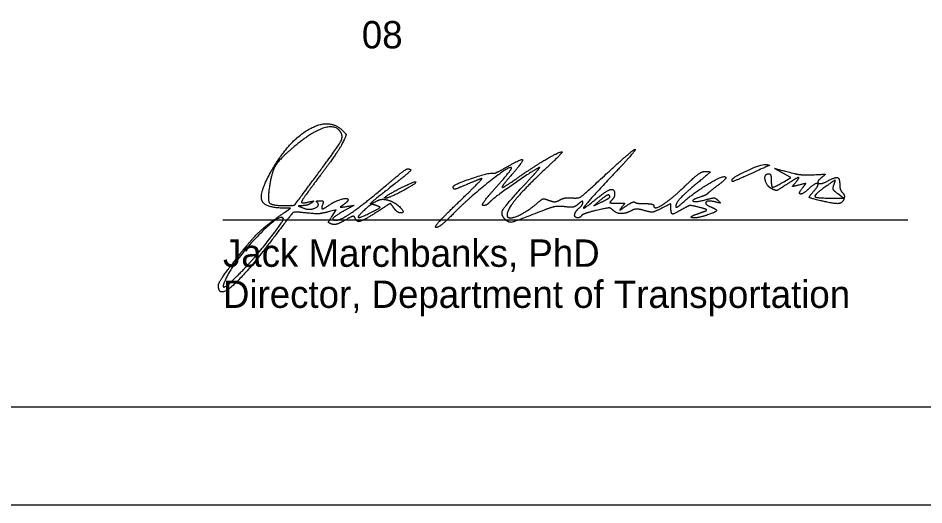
# Model space of a CAD drawing. Extents: x 39.5 to 73.5, y 15.6 to 37.6.
# Drawn here: x 65.326 to 69.955, y 15.601 to 18.089 of the extents above; entities that cross this region are included whole.
import ezdxf

# ---------------------------------------------------------------- set-up
doc = ezdxf.new("R2010")
doc.units = 0
for name, color, linetype in [('GM_X_City_Street', 7, 'Continuous'), ('GM_X_Hydro_Text', 7, 'Continuous'), ('GM_X_Interstate_Route', 7, 'Continuous'), ('GM_X_Major_River_Text', 7, 'Continuous')]:
    doc.layers.add(name, color=color, linetype=linetype)

msp = doc.modelspace()

# ---------------------------------------------------------------- linework, layer by layer
at = {"layer": 'GM_X_City_Street'}
msp.add_lwpolyline([(41.5012, 37.1011), (73.0012, 37.1011), (73.0012, 16.1011), (41.5012, 16.1011)], close=True, dxfattribs=at)
at = {"layer": 'GM_X_Hydro_Text'}
msp.add_lwpolyline([(39.5012, 15.6011), (73.5012, 15.6011), (73.5012, 37.6011), (39.5012, 37.6011)], close=True, dxfattribs=at)
at = {"layer": 'GM_X_Interstate_Route'}
for p, q in [((66.8356, 17.2629), (66.8356, 17.2629)), ((68.9749, 17.2621), (68.9749, 17.2621)), ((67.201, 17.1731), (67.201, 17.1731)), ((68.3499, 17.1751), (68.3499, 17.1751)), ((67.1562, 17.1314), (67.1562, 17.1314)), ((67.5728, 17.144), (67.5728, 17.144)), ((69.4274, 17.1558), (69.4274, 17.1558))]:
    msp.add_line(p, q, dxfattribs=at)
for points in [[(69.2387, 17.2525), (69.2751, 17.274), (69.2344, 17.297)], [(69.4874, 17.169), (69.5437, 17.1691), (69.515, 17.1912)], [(68.2982, 17.1554), (68.2687, 17.1298), (68.3093, 17.1495)], [(66.688, 17.096), (66.7187, 17.1172), (66.6808, 17.1179)], [(66.9309, 17.0761), (66.9521, 17.1085), (66.9104, 17.0984)]]:
    msp.add_lwpolyline(points, dxfattribs=at)
for points in [[(66.6243, 17.3137), (66.7106, 17.4641), (66.9187, 17.5801), (66.9844, 17.5144)], [(66.9754, 17.5052), (66.9494, 17.5473), (66.8234, 17.5061), (66.728, 17.4245)], [(66.8356, 17.2629), (66.957, 17.4264), (66.9894, 17.4826), (66.9754, 17.5052)], [(66.9844, 17.5144), (67.0031, 17.4957), (67.0032, 17.4906), (66.9849, 17.4522)], [(66.9849, 17.4522), (66.9739, 17.4292), (66.9222, 17.3536), (66.8699, 17.2843)], [(66.728, 17.4245), (66.6614, 17.3674), (66.6225, 17.3033), (66.6114, 17.2321)], [(67.8781, 17.2722), (67.9586, 17.3288), (68.0899, 17.406), (68.1056, 17.406)], [(68.1056, 17.406), (68.1105, 17.406), (68.0692, 17.3634), (68.0138, 17.3113)], [(68.3323, 17.2926), (68.4073, 17.3617), (68.4734, 17.4183), (68.4791, 17.4184)], [(68.4791, 17.4184), (68.4848, 17.4184), (68.4328, 17.3583), (68.3635, 17.2847)], [(67.8191, 17.3257), (67.8979, 17.3718), (67.9101, 17.3586), (67.8509, 17.2913)], [(66.6808, 17.1179), (66.5829, 17.1195), (66.5595, 17.2007), (66.6243, 17.3137)], [(67.2145, 17.2402), (67.2649, 17.2831), (67.3104, 17.3182), (67.3156, 17.3183)], [(67.3156, 17.3183), (67.3404, 17.3188), (67.3171, 17.2933), (67.2312, 17.226)], [(67.8472, 17.3254), (67.8376, 17.335), (67.6278, 17.1681), (67.5499, 17.0888)], [(67.9874, 17.325), (67.9384, 17.2972), (67.7501, 17.165), (67.7368, 17.149)], [(67.7535, 17.2964), (67.759, 17.2946), (67.7886, 17.3078), (67.8191, 17.3257)], [(67.7694, 17.225), (67.8157, 17.2768), (67.8507, 17.3219), (67.8472, 17.3254)], [(67.9223, 17.246), (67.9684, 17.2953), (67.9978, 17.3308), (67.9874, 17.325)], [(68.9749, 17.2621), (68.9749, 17.2745), (69.1278, 17.3448), (69.1467, 17.3411)], [(69.1467, 17.3411), (69.1674, 17.3371), (69.1681, 17.3375), (69.0465, 17.2828)], [(69.2344, 17.297), (69.1916, 17.3211), (69.1906, 17.3211), (69.2937, 17.2947)], [(66.8699, 17.2843), (66.8177, 17.2149), (66.7749, 17.1543), (66.7749, 17.1495)], [(67.5501, 17.2279), (67.5504, 17.2384), (67.7377, 17.3016), (67.7535, 17.2964)], [(67.5728, 17.144), (67.6438, 17.2125), (67.6991, 17.2685), (67.6957, 17.2685)], [(67.6957, 17.2685), (67.6923, 17.2685), (67.6633, 17.2573), (67.6312, 17.2435)], [(67.8509, 17.2913), (67.8229, 17.2595), (67.7999, 17.2298), (67.7999, 17.2253)], [(67.7999, 17.2253), (67.7999, 17.2209), (67.8351, 17.242), (67.8781, 17.2722)], [(68.0138, 17.3113), (67.9142, 17.2176), (67.8249, 17.1094), (67.8249, 17.0825)], [(68.1573, 17.1702), (68.1908, 17.1674), (68.2143, 17.1838), (68.3323, 17.2926)], [(68.3635, 17.2847), (68.2339, 17.1471), (68.2019, 17.0999), (68.284, 17.1676)], [(68.7218, 17.1451), (68.7754, 17.1939), (68.9224, 17.2839), (68.9393, 17.2783)], [(68.7406, 17.2363), (68.7858, 17.2801), (68.8229, 17.3058), (68.8406, 17.3054)], [(68.8406, 17.3054), (68.8649, 17.305), (68.8611, 17.2986), (68.8124, 17.2586)], [(68.9393, 17.2783), (68.9477, 17.2755), (68.9324, 17.2568), (68.9053, 17.2366)], [(69.0465, 17.2828), (68.9839, 17.2547), (68.9749, 17.2521), (68.9749, 17.2621)], [(69.176, 17.218), (69.1495, 17.2321), (69.1385, 17.2935), (69.1624, 17.2935)], [(69.1624, 17.2935), (69.1693, 17.2935), (69.1749, 17.2794), (69.1749, 17.2623)], [(69.2983, 17.2477), (69.3227, 17.2773), (69.307, 17.2735), (69.2507, 17.2363)], [(69.2937, 17.2947), (69.3143, 17.2894), (69.3593, 17.2867), (69.3937, 17.2886)], [(69.3937, 17.2886), (69.4486, 17.2917), (69.4534, 17.2901), (69.4336, 17.2753)], [(69.4336, 17.2753), (69.4047, 17.2538), (69.4277, 17.2374), (69.4614, 17.2554)], [(69.4614, 17.2554), (69.5016, 17.277), (69.5249, 17.2712), (69.5249, 17.2398)], [(66.6114, 17.2321), (66.6, 17.1587), (66.6214, 17.131), (66.6895, 17.131)], [(66.6895, 17.131), (66.7362, 17.131), (66.7407, 17.1351), (66.8356, 17.2629)], [(66.9531, 17.056), (66.9762, 17.056), (67.1022, 17.1448), (67.2145, 17.2402)], [(67.2312, 17.226), (67.138, 17.153), (67.1165, 17.1314), (67.1604, 17.1549)], [(67.201, 17.1731), (67.2214, 17.1909), (67.3534, 17.2567), (67.3586, 17.2516)], [(67.3586, 17.2516), (67.3647, 17.2454), (67.2221, 17.1685), (67.2045, 17.1685)], [(67.6312, 17.2435), (67.5686, 17.2167), (67.5498, 17.2131), (67.5501, 17.2279)], [(67.7035, 17.131), (67.6932, 17.131), (67.7221, 17.1723), (67.7694, 17.225)], [(67.8152, 17.0604), (67.79, 17.0856), (67.8189, 17.1357), (67.9223, 17.246)], [(68.5749, 17.1295), (68.5749, 17.1067), (68.6702, 17.1681), (68.7406, 17.2363)], [(68.8124, 17.2586), (68.7384, 17.1976), (68.6874, 17.1441), (68.6874, 17.1273)], [(68.9053, 17.2366), (68.8783, 17.2164), (68.8534, 17.1964), (68.8499, 17.1921)], [(69.1749, 17.2623), (69.1749, 17.2254), (69.1892, 17.2233), (69.2387, 17.2525)], [(69.2507, 17.2363), (69.2106, 17.2098), (69.1974, 17.2065), (69.176, 17.218)], [(69.3177, 17.236), (69.2847, 17.2277), (69.2828, 17.2288), (69.2983, 17.2477)], [(69.3378, 17.2252), (69.3524, 17.2428), (69.3502, 17.244), (69.3177, 17.236)], [(69.3665, 17.2165), (69.3346, 17.1865), (69.3116, 17.1936), (69.3378, 17.2252)], [(69.3917, 17.2038), (69.4222, 17.2375), (69.4005, 17.2484), (69.3665, 17.2165)], [(69.4952, 17.2367), (69.5051, 17.2625), (69.4969, 17.2594), (69.4343, 17.2138)], [(69.515, 17.1912), (69.4946, 17.2069), (69.4888, 17.2201), (69.4952, 17.2367)], [(69.5249, 17.2398), (69.5249, 17.2239), (69.5313, 17.2046), (69.5391, 17.1968)], [(67.2045, 17.1685), (67.1997, 17.1685), (67.1981, 17.1706), (67.201, 17.1731)], [(68.284, 17.1676), (68.3324, 17.2075), (68.3749, 17.2179), (68.3749, 17.1898)], [(68.3499, 17.1751), (68.3499, 17.1886), (68.3259, 17.1794), (68.2982, 17.1554)], [(68.3093, 17.1495), (68.3317, 17.1603), (68.3499, 17.1718), (68.3499, 17.1751)], [(68.3749, 17.1898), (68.3749, 17.1808), (68.3682, 17.1668), (68.3599, 17.1585)], [(68.8156, 17.1756), (68.766, 17.1601), (68.7855, 17.1465), (68.8374, 17.1603)], [(68.8499, 17.1921), (68.8465, 17.1879), (68.831, 17.1804), (68.8156, 17.1756)], [(69.4274, 17.1558), (69.3727, 17.1688), (69.367, 17.1765), (69.3917, 17.2038)], [(69.4343, 17.2138), (69.3916, 17.1827), (69.408, 17.1689), (69.4874, 17.169)], [(69.5391, 17.1968), (69.5469, 17.1891), (69.5499, 17.1739), (69.5457, 17.1631)], [(66.7812, 17.1304), (66.7588, 17.1295), (66.7592, 17.1282), (66.7854, 17.1177)], [(66.7749, 17.1495), (66.7749, 17.1447), (66.7904, 17.1444), (66.8093, 17.1488)], [(66.8249, 17.1441), (66.8146, 17.1371), (66.7949, 17.1309), (66.7812, 17.1304)], [(66.7854, 17.1177), (66.8152, 17.1058), (66.8715, 17.1303), (66.854, 17.1478)], [(66.8093, 17.1488), (66.8348, 17.1547), (66.8389, 17.1535), (66.8249, 17.1441)], [(66.854, 17.1478), (66.8495, 17.1523), (66.8558, 17.156), (66.8679, 17.156)], [(66.8679, 17.156), (66.8825, 17.156), (66.8876, 17.1496), (66.8829, 17.1373)], [(66.8829, 17.1373), (66.874, 17.114), (66.8868, 17.1133), (66.919, 17.1354)], [(66.919, 17.1354), (66.9479, 17.1552), (67.0124, 17.1727), (67.0124, 17.1607)], [(66.9908, 17.1367), (66.9719, 17.1229), (66.9739, 17.1216), (67.0064, 17.1265)], [(67.0124, 17.1607), (67.0124, 17.1562), (67.0027, 17.1454), (66.9908, 17.1367)], [(67.0064, 17.1265), (67.0432, 17.1321), (67.0431, 17.1318), (66.9976, 17.1067)], [(67.1562, 17.1314), (67.139, 17.1378), (67.1225, 17.1326), (67.1031, 17.1149)], [(67.1281, 17.0951), (67.1744, 17.1188), (67.178, 17.1234), (67.1562, 17.1314)], [(67.1604, 17.1549), (67.1731, 17.1617), (67.197, 17.1638), (67.2135, 17.1596)], [(67.2466, 17.1182), (67.2297, 17.1422), (67.2277, 17.1418), (67.1619, 17.0994)], [(67.2135, 17.1596), (67.2496, 17.1504), (67.308, 17.0935), (67.2813, 17.0935)], [(67.4624, 17.0192), (67.4521, 17.0194), (67.5018, 17.0756), (67.5728, 17.144)], [(67.7368, 17.149), (67.7286, 17.1391), (67.7136, 17.131), (67.7035, 17.131)], [(67.843, 17.0685), (67.8647, 17.0685), (67.946, 17.1137), (67.9824, 17.146)], [(67.9824, 17.146), (68.0027, 17.164), (68.0156, 17.1667), (68.0393, 17.1577)], [(68.1204, 17.125), (68.0911, 17.1288), (68.0513, 17.1223), (68.0148, 17.1079)], [(68.0393, 17.1577), (68.0595, 17.15), (68.0783, 17.1507), (68.0943, 17.1597)], [(68.0943, 17.1597), (68.1077, 17.1673), (68.1361, 17.172), (68.1573, 17.1702)], [(68.1899, 17.1395), (68.1742, 17.1253), (68.1529, 17.1209), (68.1204, 17.125)], [(68.2124, 17.147), (68.2124, 17.1541), (68.2023, 17.1507), (68.1899, 17.1395)], [(68.1937, 17.1185), (68.204, 17.1271), (68.2124, 17.1399), (68.2124, 17.147)], [(68.3599, 17.1585), (68.3483, 17.1468), (68.3542, 17.1435), (68.3865, 17.1435)], [(68.3865, 17.1435), (68.424, 17.1435), (68.4264, 17.1415), (68.4108, 17.1221)], [(68.4108, 17.1221), (68.3988, 17.1071), (68.4053, 17.1089), (68.4326, 17.128)], [(68.4326, 17.128), (68.454, 17.143), (68.4747, 17.1521), (68.4786, 17.1481)], [(68.4786, 17.1481), (68.4826, 17.1442), (68.5058, 17.141), (68.5304, 17.141)], [(68.5304, 17.141), (68.5549, 17.141), (68.5749, 17.1358), (68.5749, 17.1295)], [(68.6624, 17.1169), (68.6624, 17.1398), (68.6614, 17.1398), (68.6152, 17.117)], [(68.6874, 17.1273), (68.6874, 17.1199), (68.7029, 17.1279), (68.7218, 17.1451)], [(68.8076, 17.1219), (68.7687, 17.1318), (68.752, 17.1302), (68.7244, 17.1139)], [(68.8374, 17.1603), (68.8757, 17.1705), (68.891, 17.1699), (68.903, 17.1577)], [(68.8843, 17.1502), (68.8476, 17.1593), (68.8343, 17.1362), (68.8687, 17.123)], [(68.903, 17.1577), (68.9157, 17.1448), (68.9121, 17.1434), (68.8843, 17.1502)], [(69.5457, 17.1631), (69.5377, 17.142), (69.4965, 17.1395), (69.4274, 17.1558)], [(66.4371, 16.8538), (66.5147, 16.9542), (66.5948, 17.0315), (66.688, 17.096)], [(66.7692, 17.0961), (66.7358, 17.0994), (66.7241, 17.0889), (66.6474, 16.9873)], [(66.9104, 17.0984), (66.8701, 17.0886), (66.8477, 17.0883), (66.7692, 17.0961)], [(66.9976, 17.1067), (66.9466, 17.0785), (66.9268, 17.056), (66.9531, 17.056)], [(67.1619, 17.0994), (67.0931, 17.0551), (67.0556, 17.0453), (67.0475, 17.0697)], [(67.1031, 17.1149), (67.0588, 17.0744), (67.0701, 17.0655), (67.1281, 17.0951)], [(67.2813, 17.0935), (67.2717, 17.0935), (67.2561, 17.1046), (67.2466, 17.1182)], [(67.5499, 17.0888), (67.5121, 17.0503), (67.4728, 17.019), (67.4624, 17.0192)], [(68.0148, 17.1079), (67.8687, 17.0502), (67.8337, 17.0419), (67.8152, 17.0604)], [(67.8249, 17.0825), (67.8249, 17.0748), (67.8331, 17.0685), (67.843, 17.0685)], [(68.1867, 17.0685), (68.1683, 17.0685), (68.1729, 17.1013), (68.1937, 17.1185)], [(68.281, 17.106), (68.2427, 17.0968), (68.2084, 17.0846), (68.2049, 17.0789)], [(68.3653, 17.1081), (68.3542, 17.1192), (68.3342, 17.1187), (68.281, 17.106)], [(68.4617, 17.1056), (68.4309, 17.0891), (68.3831, 17.0904), (68.3653, 17.1081)], [(68.5261, 17.1057), (68.4993, 17.1134), (68.4762, 17.1133), (68.4617, 17.1056)], [(68.6152, 17.117), (68.5778, 17.0985), (68.5593, 17.0962), (68.5261, 17.1057)], [(68.7244, 17.1139), (68.6793, 17.0873), (68.6624, 17.0881), (68.6624, 17.1169)], [(68.8436, 17.081), (68.797, 17.0656), (68.7496, 17.0713), (68.7937, 17.087)], [(68.7937, 17.087), (68.8074, 17.0919), (68.8271, 17.099), (68.8374, 17.1027)], [(68.8374, 17.1027), (68.8488, 17.1069), (68.8371, 17.1144), (68.8076, 17.1219)], [(68.8687, 17.123), (68.8992, 17.1113), (68.8903, 17.0964), (68.8436, 17.081)], [(66.6809, 17.0667), (66.66, 17.0877), (66.4414, 16.862), (66.3951, 16.7716)], [(66.4652, 16.7904), (66.5328, 16.8594), (66.6886, 17.0591), (66.6809, 17.0667)], [(66.9297, 17.0361), (66.9116, 17.0431), (66.9117, 17.0467), (66.9309, 17.0761)], [(66.9963, 17.0559), (66.9707, 17.0408), (66.9407, 17.0319), (66.9297, 17.0361)], [(67.0475, 17.0697), (67.0446, 17.0782), (67.0254, 17.0731), (66.9963, 17.0559)], [(68.2049, 17.0789), (68.2013, 17.0732), (68.1932, 17.0685), (68.1867, 17.0685)], [(66.6474, 16.9873), (66.495, 16.7852), (66.3499, 16.6565), (66.3499, 16.7235)], [(66.3499, 16.7235), (66.3499, 16.7332), (66.3892, 16.7918), (66.4371, 16.8538)], [(66.3951, 16.7716), (66.3639, 16.7107), (66.3955, 16.7191), (66.4652, 16.7904)]]:
    msp.add_open_spline(points, degree=2, dxfattribs=at)
at = {"layer": 'GM_X_Major_River_Text'}
msp.add_line((66.3734, 17.0579), (69.8734, 17.0579), dxfattribs=at)

# ---------------------------------------------------------------- texts
at = {"layer": 'GM_X_Interstate_Route'}
for s, p in [('              08', (66.3547, 17.9342)), ('Jack Marchbanks, PhD', (66.3734, 16.8179)), ('Director, Department of Transportation', (66.3734, 16.6079))]:
    msp.add_text(s, height=0.14, dxfattribs=at).set_placement(p)

doc.saveas('drawing.dxf')
